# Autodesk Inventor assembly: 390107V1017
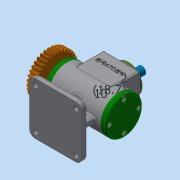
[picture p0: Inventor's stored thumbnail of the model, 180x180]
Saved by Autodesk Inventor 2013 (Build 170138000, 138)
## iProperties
Created: 2019-01
Part Number: 390107V1017
Document SubType Name: Assembly
Designer: dgall
Mass: 1743.43 g
Surface Area: 1517.22 cm^2
Volume: 491.998 cm^3
Density: 3.54357 g/cm^3
Author: dgall
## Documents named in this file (18)
- C:\Users\dgall\Desktop\390107V1017\390107V1017.iam
- C:\Users\dgall\Desktop\390107V1017\본체.ipt
- C:\Users\dgall\Desktop\390107V1017\베어링 6203.ipt
- C:\Users\dgall\Desktop\390107V1017\뒤커버.ipt
- C:\Users\dgall\Desktop\390107V1017\앞커버.ipt
- C:\Users\dgall\Desktop\390107V1017\편심축.ipt
- C:\Users\dgall\Desktop\390107V1017\오일 실 17 30 5.ipt
- C:\Users\dgall\Desktop\390107V1017\스퍼기어.ipt
- C:\Users\dgall\Desktop\390107V1017\키 4x4x12.ipt
- C:\Users\dgall\Desktop\390107V1017\볼트 M4.ipt
- C:\Users\dgall\Desktop\390107V1017\스프링와셔.ipt
- C:\Users\dgall\Desktop\390107V1017\평와셔.ipt
- C:\Users\dgall\Desktop\390107V1017\가변스프링.ipt
- C:\Users\dgall\Desktop\390107V1017\부시.ipt
- C:\Users\dgall\Desktop\390107V1017\상부커버.ipt
- C:\Users\dgall\Desktop\390107V1017\스프링조립용 와셔.ipt
- C:\Users\dgall\Desktop\390107V1017\슬라이더.ipt
- C:\Users\dgall\Desktop\390107V1017\멈춤링.ipt
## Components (1 placed, 1 different names)
1. 가변스프링:1
